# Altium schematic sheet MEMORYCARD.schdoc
size 356 x 288 mm
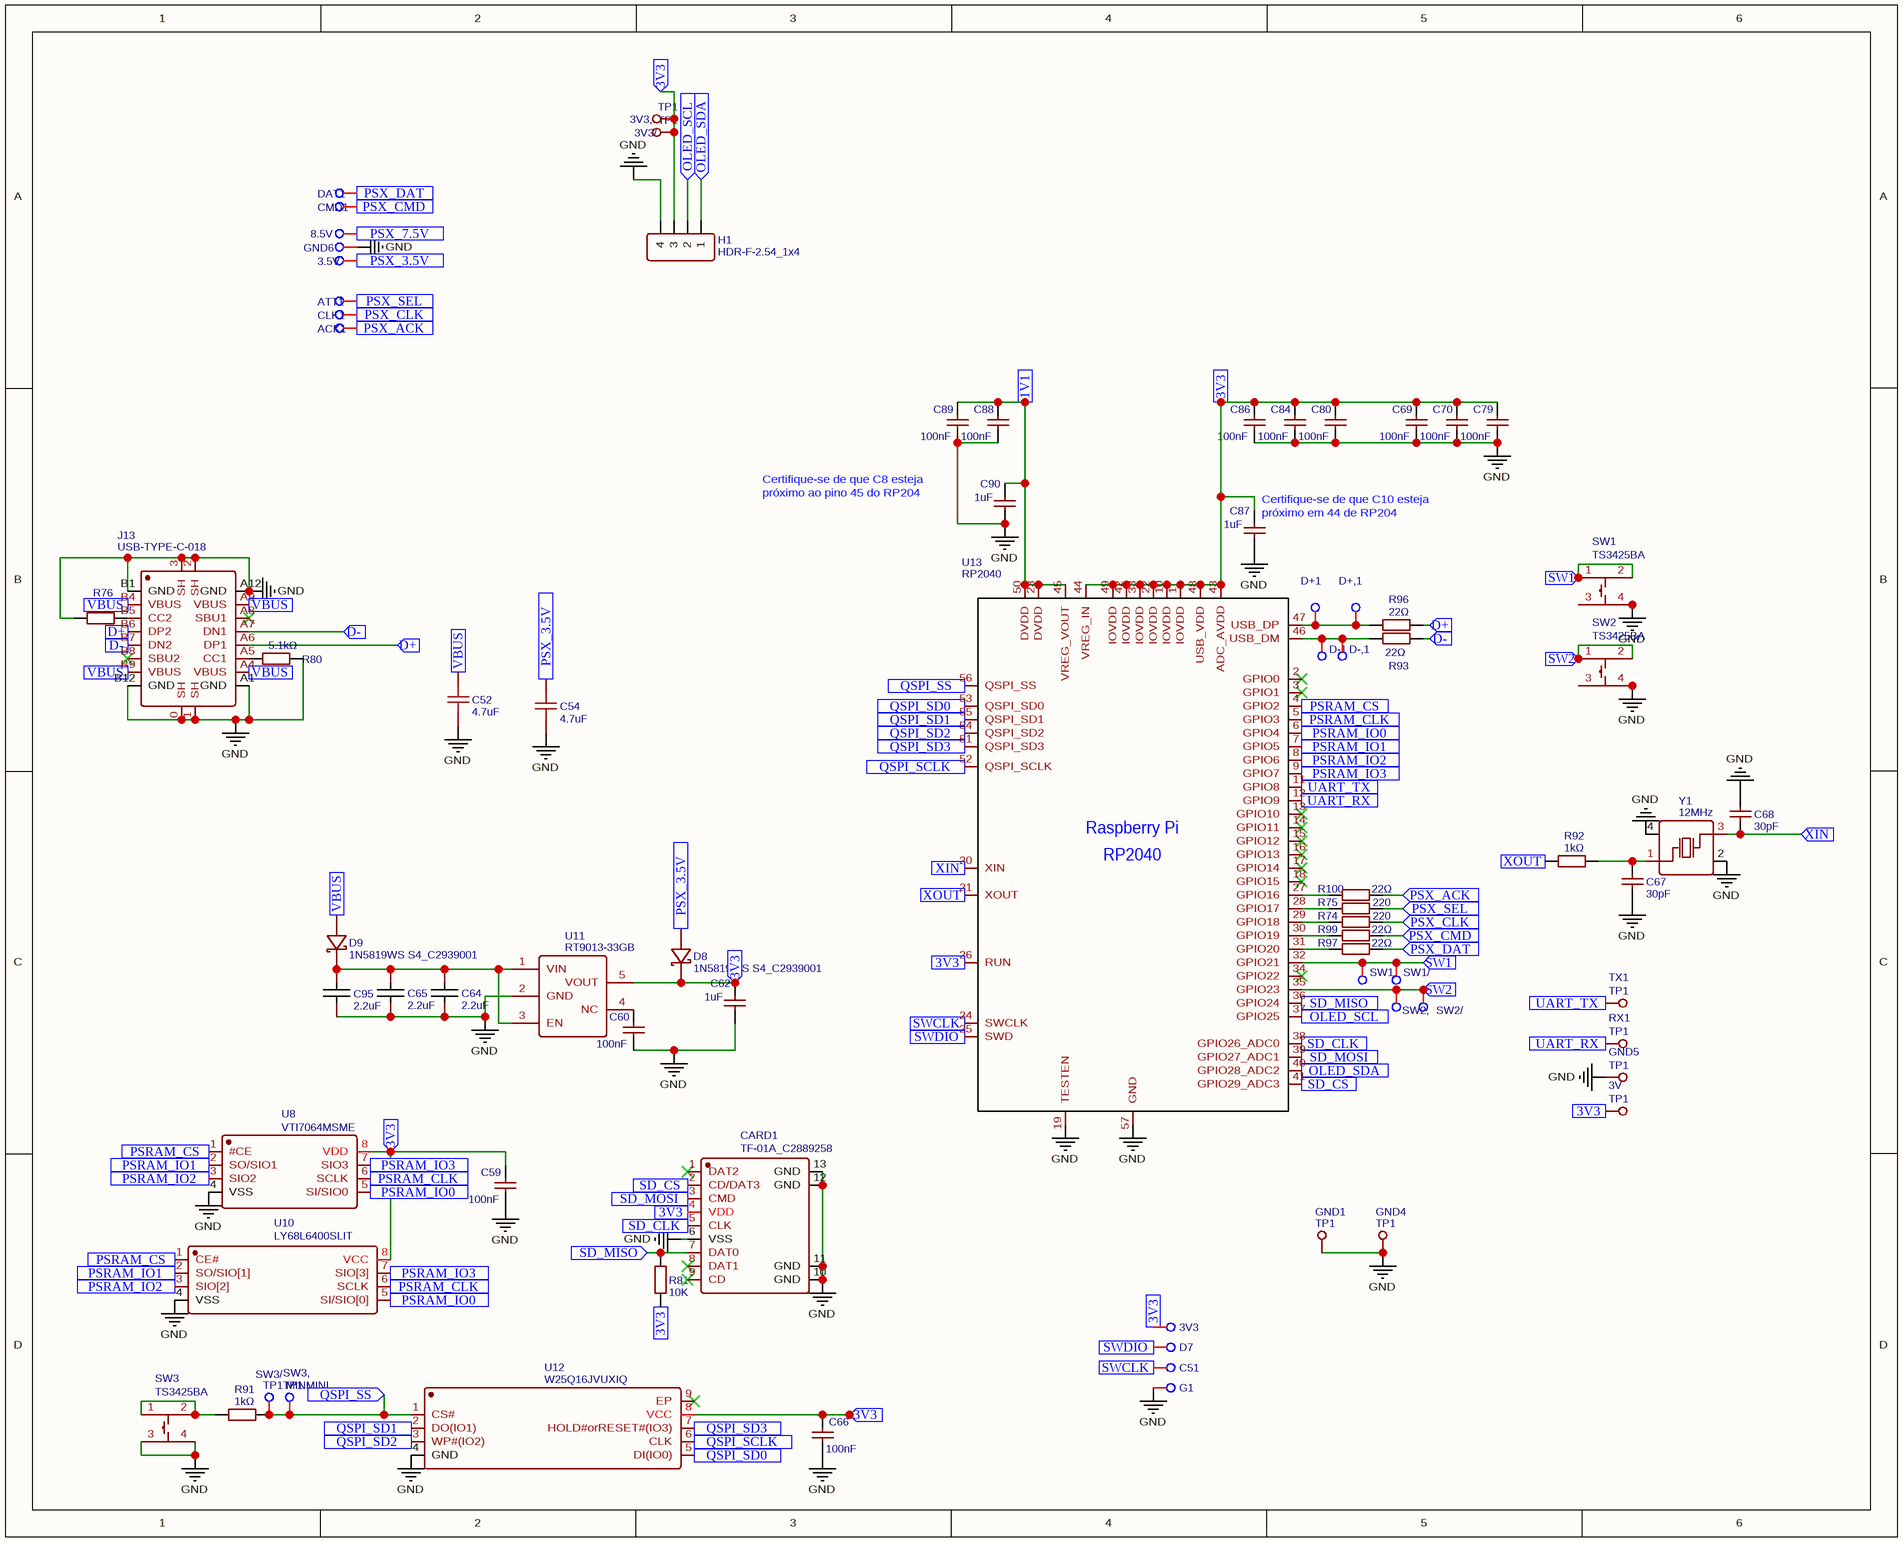
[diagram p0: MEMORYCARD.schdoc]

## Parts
3.5V  TP1 MINI  [TP1 MINI]  (value not drawn)
3V  TP1  [TP1]
3V3  TP1 MINI  [TP1 MINI]  (value not drawn)
3V3,  TP1  [TP1]
3V3/  TP1  [TP1]
8.5V  TP1 MINI  [TP1 MINI]  (value not drawn)
ACK1  TP1 MINI  [TP1 MINI]  (value not drawn)
ATT1  TP1 MINI  [TP1 MINI]  (value not drawn)
C51  TP1 MINI  [TP1 MINI]  (value not drawn)
C52  4.7uF  [C0402]
C54  4.7uF  [C0402]
C59  100nF  [C0402_NEW]
C60  100nF  [C0402_NEW]
C62  1uF  [C0402]
C64  2.2uF  [C0402]
C65  2.2uF  [C0402]
C66  100nF  [C0402_NEW]
C67  30pF  [C0402]
C68  30pF  [C0402]
C69  100nF  [C0402_NEW]
C70  100nF  [C0402_NEW]
C79  100nF  [C0402_NEW]
C80  100nF  [C0402_NEW]
C84  100nF  [C0402_NEW]
C86  100nF  [C0402_NEW]
C87  1uF  [C0402]
C88  100nF  [C0402_NEW]
C89  100nF  [C0402_NEW]
C90  1uF  [C0402]
C95  2.2uF  [C0402]
CARD1  TF-01A_C2889258  [TF-SMD_TF-02]
CLK1  TP1 MINI  [TP1 MINI]  (value not drawn)
CMD1  TP1 MINI  [TP1 MINI]  (value not drawn)
D7  SWDIO  [TP1 MINI]  (value not drawn)
D8  1N5819WS S4_C2939001  [SOD-323_L1.7-W1.3-LS2.6-RD-1]
D9  1N5819WS S4_C2939001  [SOD-323_L1.7-W1.3-LS2.6-RD-1]
D+1  NO  [TP1 MINI]  (value not drawn)
D+,1  NO  [TP1 MINI]  (value not drawn)
D-1  NO  [TP1 MINI]  (value not drawn)
D-,1  NO  [TP1 MINI]  (value not drawn)
DAT1  TP1 MINI  [TP1 MINI]  (value not drawn)
G1  TP1 MINI  [TP1 MINI]  (value not drawn)
GND1  TP1  [TP1]
GND4  TP1  [TP1]
GND5  TP1  [TP1]
GND6  TP1 MINI  [TP1 MINI]  (value not drawn)
H1  HDR-F-2.54_1x4  [HDR-F-2.54_1X4]
J13  USB-TYPE-C-018  [USB-C_SMD-TYPE-C-31-M-12]
R74  220  [R0402]
R75  220  [R0402]
R76  5.1kΩ  [R0402]
R80  5.1kΩ  [R0402]
R81  10K  [R0402]
R91  1kΩ  [R0402]
R92  1kΩ  [R0402]
R93  22Ω  [R0402]
R96  22Ω  [R0402]
R97  22Ω  [R0402]
R99  22Ω  [R0402]
R100  22Ω  [R0402]
RX1  TP1  [TP1]
SW1  TS3425BA  [SW-SMD_4P-L4.2-W3.2-P2.15-LS4.6-1]
SW1,  NO  [TP1 MINI]  (value not drawn)
SW1/  NO  [TP1 MINI]  (value not drawn)
SW2  TS3425BA  [SW-SMD_4P-L4.2-W3.2-P2.15-LS4.6-1]
SW2,  NO  [TP1 MINI]  (value not drawn)
SW2/  NO  [TP1 MINI]  (value not drawn)
SW3  TS3425BA  [SW-SMD_4P-L4.2-W3.2-P2.15-LS4.6-1]
SW3,  TP1 MINI  [TP1 MINI]
SW3/  TP1 MINI  [TP1 MINI]
TX1  TP1  [TP1]
U8  VTI7064MSME  [SOIC-8_L4.9-W3.9-P1.27-LS6.0-BL]
U10  LY68L6400SLIT  [SOP-8_L4.9-W3.9-P1.27-LS6.0-BL]
U11  RT9013-33GB  [SOT-23-5_L3.0-W1.7-P0.95-LS2.8-BL]
U12  W25Q16JVUXIQ  [USON-8_L3.0-W2.0-P0.50-BL-EP]
U13  RP2040  [LQFN-56_L7.0-W7.0-P0.4-EP]
Y1  12MHz  [OSC-SMD_4P-L3.2-W2.5-BL]

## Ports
1V1 (in), 3V3 (in), D+ (in), D- (in), OLED_SCL (in), OLED_SDA (in), PSRAM_CLK (in), PSRAM_CS (in), PSRAM_IO0 (in), PSRAM_IO1 (in), PSRAM_IO2 (in), PSRAM_IO3 (in), PSX_3.5V (in), PSX_7.5V (in), PSX_ACK (in), PSX_CLK (in), PSX_CMD (in), PSX_DAT (in), PSX_SEL (in), QSPI_SCLK (in), QSPI_SD0 (in), QSPI_SD1 (in), QSPI_SD2 (in), QSPI_SD3 (in), QSPI_SS (in), SD_CLK (in), SD_CS (in), SD_MISO (in), SD_MOSI (in), SW1 (in), SW2 (in), SWCLK (in), SWDIO (in), UART_RX (in), UART_TX (in), VBUS (in), XIN (in), XOUT (in)

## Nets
GND: C52.1 C54.1 C59.1 C60.1 C62.1 C64.1 C65.1 C66.1 C67.1 C68.2 C69.1 C70.1 C79.1 C80.1 C84.1 C86.1 C87.1 C88.1 C89.1 C90.1 C95.1 CARD1.6(VSS) CARD1.10(GND) CARD1.11(GND) CARD1.12(GND) CARD1.13(GND) G1.1 GND1.1 GND4.1 GND5.1 GND6.1 H1.4 J13.0(SH) J13.1(SH) J13.2(SH) J13.3(SH) J13.A1(GND) J13.A12(GND) J13.B1(GND) J13.B12(GND) R76.1 R80.2 SW1.3 SW1.4 SW2.3 SW2.4 SW3.3 SW3.4 U8.4(VSS) U10.4(VSS) U11.2(GND) U12.4(GND) U13.19(TESTEN) U13.57(GND) Y1.2(GND) Y1.4(GND)
1V1: C88.2 C89.2 C90.2 U13.23(DVDD) U13.45(VREG_VOUT) U13.50(DVDD) ; port 1V1
3V3: 3V.1 3V3.1 3V3,.1 3V3/.1 C59.2 C62.2 C66.2 C69.2 C70.2 C79.2 C80.2 C84.2 C86.2 C87.2 CARD1.4(VDD) D8.1(K) H1.3 R81.1 U8.8(VDD) U10.8(VCC) U11.5(VOUT) U12.8(VCC) U13.1(IOVDD) U13.10(IOVDD) U13.22(IOVDD) U13.26(RUN) U13.33(IOVDD) U13.42(IOVDD) U13.43(ADC_AVDD) U13.44(VREG_IN) U13.48(USB_VDD) U13.49(IOVDD) ; port 3V3
D+: J13.A6(DP1) J13.B6(DP2) R96.2 ; port D+
D-: J13.A7(DN1) J13.B7(DN2) R93.2 ; port D-
OLED_SCL: H1.2 U13.37(GPIO25) ; port OLED_SCL
OLED_SDA: H1.1 U13.40(GPIO28_ADC2) ; port OLED_SDA
PSRAM_CLK: U8.6(SCLK) U10.6(SCLK) U13.5(GPIO3) ; port PSRAM_CLK
PSRAM_CS: U8.1(#CE) U10.1(CE#) U13.4(GPIO2) ; port PSRAM_CS
PSRAM_IO0: U8.5(SI/SIO0) U10.5(SI/SIO[0]) U13.6(GPIO4) ; port PSRAM_IO0
PSRAM_IO1: U8.2(SO/SIO1) U10.2(SO/SIO[1]) U13.7(GPIO5) ; port PSRAM_IO1
PSRAM_IO2: U8.3(SIO2) U10.3(SIO[2]) U13.8(GPIO6) ; port PSRAM_IO2
PSRAM_IO3: U8.7(SIO3) U10.7(SIO[3]) U13.9(GPIO7) ; port PSRAM_IO3
PSX_3.5V: 3.5V.1 C54.2 D8.2(A) ; port PSX_3.5V
PSX_7.5V: 8.5V.1 ; port PSX_7.5V
PSX_ACK: ACK1.1 R100.2 ; port PSX_ACK
PSX_CLK: CLK1.1 R74.2 ; port PSX_CLK
PSX_CMD: CMD1.1 R99.2 ; port PSX_CMD
PSX_DAT: DAT1.1 R97.2 ; port PSX_DAT
PSX_SEL: ATT1.1 R75.2 ; port PSX_SEL
QSPI_SCLK: U12.6(CLK) U13.52(QSPI_SCLK) ; port QSPI_SCLK
QSPI_SD0: U12.5(DI(IO0)) U13.53(QSPI_SD0) ; port QSPI_SD0
QSPI_SD1: U12.2(DO(IO1)) U13.55(QSPI_SD1) ; port QSPI_SD1
QSPI_SD2: U12.3(WP#(IO2)) U13.54(QSPI_SD2) ; port QSPI_SD2
QSPI_SD3: U12.7(HOLD#orRESET#(IO3)) U13.51(QSPI_SD3) ; port QSPI_SD3
QSPI_SS: R91.2 SW3,.1 SW3/.1 U12.1(CS#) U13.56(QSPI_SS) ; port QSPI_SS
SD_CLK: CARD1.5(CLK) U13.38(GPIO26_ADC0) ; port SD_CLK
SD_CS: CARD1.2(CD/DAT3) U13.41(GPIO29_ADC3) ; port SD_CS
SD_MISO: CARD1.7(DAT0) R81.2 U13.36(GPIO24) ; port SD_MISO
SD_MOSI: CARD1.3(CMD) U13.39(GPIO27_ADC1) ; port SD_MOSI
SW1: SW1.1 SW1.2 SW1,.1 SW1/.1 U13.32(GPIO21) ; port SW1
SW2: SW2.1 SW2.2 SW2,.1 SW2/.1 U13.35(GPIO23) ; port SW2
SWCLK: C51.1 U13.24(SWCLK) ; port SWCLK
SWDIO: D7.1 U13.25(SWD) ; port SWDIO
UART_RX: RX1.1 U13.12(GPIO9) ; port UART_RX
UART_TX: TX1.1 U13.11(GPIO8) ; port UART_TX
VBUS: C52.2 D9.2(A) J13.A4(VBUS) J13.A9(VBUS) J13.B4(VBUS) J13.B9(VBUS) ; port VBUS
XIN: C68.1 U13.20(XIN) Y1.3(OSC2) ; port XIN
XOUT: R92.1 U13.21(XOUT) ; port XOUT
NetC60_2: C60.2 U11.4(NC)
NetC64_2: C64.2 C65.2 C95.2 D9.1(K) U11.1(VIN) U11.3(EN)
NetC67_2: C67.2 R92.2 Y1.1(OSC1)
NetD+1_1: D+1.1 D+,1.1 R96.1 U13.47(USB_DP)
NetD-1_1: D-1.1 D-,1.1 R93.1 U13.46(USB_DM)
NetJ13_A5: J13.A5(CC1) R80.1
NetJ13_B5: J13.B5(CC2) R76.2
NetR74_1: R74.1 U13.29(GPIO18)
NetR75_1: R75.1 U13.28(GPIO17)
NetR91_1: R91.1 SW3.1 SW3.2
NetR97_1: R97.1 U13.31(GPIO20)
NetR99_1: R99.1 U13.30(GPIO19)
NetR100_1: R100.1 U13.27(GPIO16)

Not connected (* = marked no-connect by the designer): CARD1 1(DAT2)* 8(DAT1)* 9(CD)*; J13 A8(SBU1)* B8(SBU2)*; U12 9(EP)*; U13 2(GPIO0)* 3(GPIO1)* 13(GPIO10)* 14(GPIO11)* 15(GPIO12)* 16(GPIO13)* 17(GPIO14)* 18(GPIO15)* 34(GPIO22)*

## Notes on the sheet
- Certifique-se de que C8 esteja
- próximo ao pino 45 do RP204
- (near C87) próximo em 44 de RP204
- (near C87) Certifique-se de que C10 esteja

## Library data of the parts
3.5V 3V3 8.5V ACK1 ATT1 C51 CLK1 CMD1 DAT1 G1 GND6 SW3, SW3/ = TP1 MINI: Contributor: Marlon Vinicius
3V 3V3, 3V3/ GND1 GND4 GND5 RX1 TX1 = TP1: Contributor: Marlon Vinicius; Convert to PCB: Yes
C52 C54 = 4.7uF: Manufacturer: Samsung Electro-Mechanics; Manufacturer Part: CL05A475KP5NRNC; nameAlias: Capacitance; Contributor: LCSC
C59 C60 C66 C69 C70 C79 C80 C84 C86 C88 C89 = 100nF: Manufacturer Part: CL05B104KO5NNNC; Manufacturer: SAMSUNG; nameAlias: Capacitance
C62 C87 C90 = 1uF: Manufacturer Part: CL05A105KO5NNNC; Manufacturer: SAMSUNG; nameAlias: Capacitance
C64 C65 C95 = 2.2uF: Manufacturer Part: CL05A225MQ5NSNC; Manufacturer: SAMSUNG; nameAlias: Capacitance
C67 C68 = 30pF: Manufacturer: YAGEO(国巨); Manufacturer Part: CC0402JRNPO9BN300; nameAlias: Value
CARD1 = TF-01A_C2889258: Manufacturer: Yuandi(台湾元迪); Manufacturer Part: TF-01A; Contributor: LCSC
D7 = SWDIO: Contributor: Marlon Vinicius
D8 D9 = 1N5819WS S4_C2939001: Manufacturer: KUU; Contributor: lcsc
D+1 D+,1 D-1 D-,1 SW1, SW1/ SW2, SW2/ = NO: Contributor: Marlon Vinicius
H1 = HDR-F-2.54_1x4: Contributor: LCEDA_Lib
J13 = USB-TYPE-C-018: Manufacturer: DEALON(德艺隆); Contributor: LCSC
R74 R75 = 220: Manufacturer: UniOhm; Manufacturer Part: 0402WGJ0221TCE; nameAlias: Resistance (Ohms)
R76 R80 = 5.1kΩ: Manufacturer: UNI-ROYAL(厚声); Manufacturer Part: 0402WGF5101TCE; nameAlias: Value
R81 = 10K: Manufacturer: UniOhm; Manufacturer Part: 0402WGF1002TCE; nameAlias: Resistance (Ohms)
R91 R92 = 1kΩ: Manufacturer: YAGEO(国巨); Manufacturer Part: RC0402FR-071KL; nameAlias: Value
R93 R96 R97 R99 R100 = 22Ω: Manufacturer: YAGEO(国巨); Manufacturer Part: RC0402JR-0722RL; nameAlias: Value
SW1-SW3 = TS3425BA: Manufacturer: SHOU HAN(首韩); Contributor: LCSC
U8 = VTI7064MSME: Manufacturer: Vilsion; Contributor: LCSC
U10 = LY68L6400SLIT: Manufacturer: Lyontek(来扬); Contributor: LCSC
U11 = RT9013-33GB: Manufacturer: RICHTEK(立锜)
U12 = W25Q16JVUXIQ: Manufacturer: WINBOND(华邦); Contributor: lcsc
U13 = RP2040: Manufacturer: Raspberry Pi(树莓派); Contributor: LCSC
Y1 = 12MHz: Manufacturer: TAE(雅晶鑫); Manufacturer Part: TAXM12M4RDBCCT2T; nameAlias: Value; Contributor: LCSC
